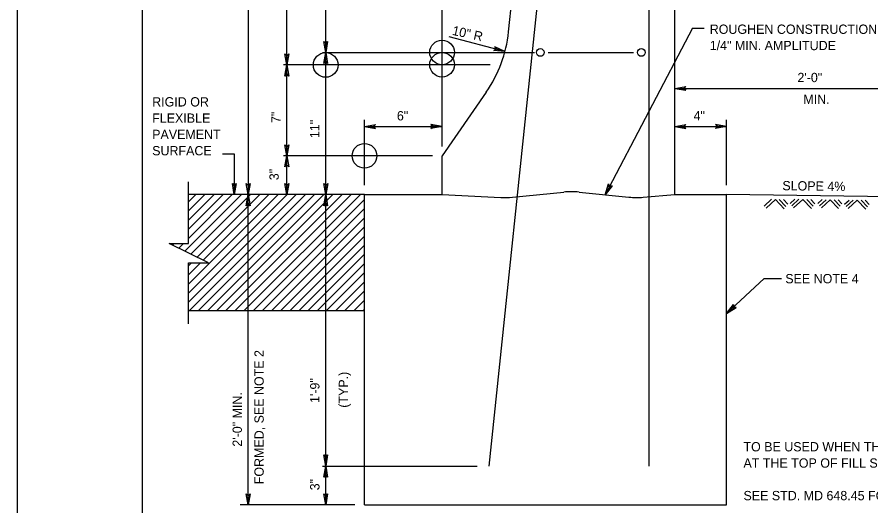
# Model space of a CAD drawing. Extents: x -32.9 to -15.8, y -6.5 to 4.5.
# Drawn here: x -24.32 to -18.82, y -1.37 to 1.78 of the extents above; entities that cross this region are included whole.
import ezdxf

# ---------------------------------------------------------------- set-up
doc = ezdxf.new("R2010")
doc.units = 0
for name, color, linetype in [('ANNO-WOUT', 7, 'Continuous'), ('BORD-LINE', 7, 'Continuous'), ('DETL-DIMS', 7, 'Continuous'), ('Level 1', 7, 'Continuous'), ('Level 10', 7, 'Continuous'), ('Level 12', 7, 'Continuous'), ('Level 6', 7, 'Continuous'), ('SECT-GRND_P', 7, 'Continuous'), ('SUBS-ASLB_P', 7, 'Continuous'), ('SUBS-FOOT_P', 7, 'Continuous'), ('SUPR-PARA_P', 7, 'Continuous'), ('SUPR-RFRC', 7, 'Continuous'), ('USER-CLIP', 7, 'Continuous')]:
    doc.layers.add(name, color=color, linetype=linetype)

msp = doc.modelspace()

# ---------------------------------------------------------------- linework, layer by layer
at = {"layer": 'ANNO-WOUT'}
for centre in [(-21.5854, 1.5558), (-22.3354, 1.4753), (-21.5854, 1.4763), (-22.0854, 0.8891)]:
    msp.add_circle(centre, 0.0795, dxfattribs=at)
at = {"layer": 'BORD-LINE'}
msp.add_lwpolyline([(-23.5151, 4.1733), (-16.1409, 4.1733), (-16.1409, -6.1798), (-23.5151, -6.1798)], close=True, dxfattribs=at)
at = {"layer": 'DETL-DIMS'}
for p, q in [((-22.3354, 1.5558), (-22.3481, 1.6273)), ((-22.3354, 1.6138), (-22.3481, 1.6273)), ((-22.3354, 1.5558), (-22.3229, 1.6273)), ((-22.3229, 1.6273), (-22.3354, 1.6138)), ((-22.5854, 1.4753), (-22.5981, 1.5468)), ((-22.5854, 1.5333), (-22.5981, 1.5468)), ((-22.5854, 1.4753), (-22.5729, 1.5468)), ((-22.5729, 1.5468), (-22.5854, 1.5333)), ((-22.3354, 1.5558), (-22.3479, 1.4843)), ((-22.3354, 1.5558), (-22.3227, 1.4843)), ((-21.2362, 1.5763), (-21.2525, 1.5675)), ((-21.1801, 1.5615), (-21.2525, 1.5675)), ((-21.1801, 1.5615), (-21.246, 1.5918)), ((-21.246, 1.5918), (-21.2362, 1.5763)), ((-22.3479, 1.4843), (-22.3354, 1.4978)), ((-22.3354, 1.4978), (-22.3227, 1.4843)), ((-22.5854, 1.4753), (-22.5979, 1.4038)), ((-22.5854, 1.4753), (-22.5727, 1.4038)), ((-22.5979, 1.4038), (-22.5854, 1.4173)), ((-22.5854, 1.4173), (-22.5727, 1.4038)), ((-20.0854, 1.3241), (-20.0139, 1.3368)), ((-20.0854, 1.3241), (-20.0139, 1.3116)), ((-20.0274, 1.3241), (-20.0139, 1.3368)), ((-20.0139, 1.3116), (-20.0274, 1.3241)), ((-22.0854, 1.0776), (-22.0139, 1.0903)), ((-22.0854, 1.0776), (-22.0139, 1.0651)), ((-22.0274, 1.0776), (-22.0139, 1.0903)), ((-22.0139, 1.0651), (-22.0274, 1.0776)), ((-21.5854, 1.0776), (-21.6569, 1.0901)), ((-21.6569, 1.0901), (-21.6434, 1.0776)), ((-21.5854, 1.0776), (-21.6569, 1.0649)), ((-21.6434, 1.0776), (-21.6569, 1.0649)), ((-20.0854, 1.0776), (-20.0139, 1.0903)), ((-20.0854, 1.0776), (-20.0139, 1.0651)), ((-20.0274, 1.0776), (-20.0139, 1.0903)), ((-20.0139, 1.0651), (-20.0274, 1.0776)), ((-19.752, 1.0776), (-19.8236, 1.0649)), ((-19.81, 1.0776), (-19.8236, 1.0649)), ((-19.752, 1.0776), (-19.8235, 1.0901)), ((-19.8235, 1.0901), (-19.81, 1.0776)), ((-22.5854, 0.8891), (-22.5981, 0.9606)), ((-22.5854, 0.9471), (-22.5981, 0.9606)), ((-22.5854, 0.8891), (-22.5729, 0.9606)), ((-22.5729, 0.9606), (-22.5854, 0.9471)), ((-22.5854, 0.8891), (-22.5979, 0.8176)), ((-22.5854, 0.8891), (-22.5727, 0.8176)), ((-22.5979, 0.8176), (-22.5854, 0.8311)), ((-22.5854, 0.8311), (-22.5727, 0.8176)), ((-22.9241, 0.6391), (-22.9368, 0.7106)), ((-22.9241, 0.6971), (-22.9368, 0.7106)), ((-22.9241, 0.6391), (-22.9116, 0.7106)), ((-22.9116, 0.7106), (-22.9241, 0.6971)), ((-22.8354, 0.6391), (-22.8481, 0.7106)), ((-22.8354, 0.6971), (-22.8481, 0.7106)), ((-22.8354, 0.6391), (-22.8229, 0.7106)), ((-22.8229, 0.7106), (-22.8354, 0.6971)), ((-22.5854, 0.6391), (-22.5981, 0.7106)), ((-22.5854, 0.6971), (-22.5981, 0.7106)), ((-22.5854, 0.6391), (-22.5729, 0.7106)), ((-22.5729, 0.7106), (-22.5854, 0.6971)), ((-22.3348, 0.6391), (-22.3475, 0.7106)), ((-22.3348, 0.6971), (-22.3475, 0.7106)), ((-22.3348, 0.6391), (-22.3223, 0.7106)), ((-22.3223, 0.7106), (-22.3348, 0.6971)), ((-20.5347, 0.6382), (-20.5128, 0.7075)), ((-20.5347, 0.6382), (-20.4905, 0.6958)), ((-20.5078, 0.6896), (-20.5128, 0.7075)), ((-20.4905, 0.6958), (-20.5078, 0.6896)), ((-22.8354, 0.6391), (-22.8479, 0.5676)), ((-22.8354, 0.6391), (-22.8227, 0.5676)), ((-22.3354, 0.6391), (-22.3479, 0.5676)), ((-22.3354, 0.6391), (-22.3227, 0.5676)), ((-22.8479, 0.5676), (-22.8354, 0.5811)), ((-22.8354, 0.5811), (-22.8227, 0.5676)), ((-22.3479, 0.5676), (-22.3354, 0.5811)), ((-22.3354, 0.5811), (-22.3227, 0.5676)), ((-19.752, -0.1283), (-19.7084, -0.0702)), ((-19.752, -0.1283), (-19.6912, -0.0887)), ((-19.7096, -0.0887), (-19.7084, -0.0702)), ((-19.6912, -0.0887), (-19.7096, -0.0887)), ((-22.3354, -1.1109), (-22.3481, -1.0394)), ((-22.3354, -1.0529), (-22.3481, -1.0394)), ((-22.3354, -1.1109), (-22.3229, -1.0394)), ((-22.3229, -1.0394), (-22.3354, -1.0529)), ((-22.3354, -1.1109), (-22.3479, -1.1824)), ((-22.3354, -1.1109), (-22.3227, -1.1824)), ((-22.3479, -1.1824), (-22.3354, -1.1689)), ((-22.3354, -1.1689), (-22.3227, -1.1824)), ((-22.8354, -1.3609), (-22.8481, -1.2894)), ((-22.8354, -1.3029), (-22.8481, -1.2894)), ((-22.8354, -1.3609), (-22.8229, -1.2894)), ((-22.8229, -1.2894), (-22.8354, -1.3029)), ((-22.3354, -1.3609), (-22.3481, -1.2894)), ((-22.3354, -1.3029), (-22.3481, -1.2894)), ((-22.3354, -1.3609), (-22.3229, -1.2894)), ((-22.3229, -1.2894), (-22.3354, -1.3029))]:
    msp.add_line(p, q, dxfattribs=at)
for points in [[(-22.3229, 1.6273), (-22.3354, 1.5558), (-22.3481, 1.6273), (-22.3354, 1.6138)], [(-22.5729, 1.5468), (-22.5854, 1.4753), (-22.5981, 1.5468), (-22.5854, 1.5333)], [(-22.3479, 1.4843), (-22.3354, 1.5558), (-22.3227, 1.4843), (-22.3354, 1.4978)], [(-21.246, 1.5918), (-21.1801, 1.5615), (-21.2525, 1.5675), (-21.2362, 1.5763)], [(-22.5979, 1.4038), (-22.5854, 1.4753), (-22.5727, 1.4038), (-22.5854, 1.4173)], [(-20.0139, 1.3116), (-20.0854, 1.3241), (-20.0139, 1.3368), (-20.0274, 1.3241)], [(-22.0139, 1.0651), (-22.0854, 1.0776), (-22.0139, 1.0903), (-22.0274, 1.0776)], [(-21.6569, 1.0901), (-21.5854, 1.0776), (-21.6569, 1.0649), (-21.6434, 1.0776)], [(-20.0139, 1.0651), (-20.0854, 1.0776), (-20.0139, 1.0903), (-20.0274, 1.0776)], [(-19.8235, 1.0901), (-19.752, 1.0776), (-19.8236, 1.0649), (-19.81, 1.0776)], [(-22.5729, 0.9606), (-22.5854, 0.8891), (-22.5981, 0.9606), (-22.5854, 0.9471)], [(-22.5979, 0.8176), (-22.5854, 0.8891), (-22.5727, 0.8176), (-22.5854, 0.8311)], [(-22.9116, 0.7106), (-22.9241, 0.6391), (-22.9368, 0.7106), (-22.9241, 0.6971)], [(-22.8229, 0.7106), (-22.8354, 0.6391), (-22.8481, 0.7106), (-22.8354, 0.6971)], [(-22.5729, 0.7106), (-22.5854, 0.6391), (-22.5981, 0.7106), (-22.5854, 0.6971)], [(-22.3223, 0.7106), (-22.3348, 0.6391), (-22.3475, 0.7106), (-22.3348, 0.6971)], [(-20.4905, 0.6958), (-20.5347, 0.6382), (-20.5128, 0.7075), (-20.5078, 0.6896)], [(-22.8479, 0.5676), (-22.8354, 0.6391), (-22.8227, 0.5676), (-22.8354, 0.5811)], [(-22.3479, 0.5676), (-22.3354, 0.6391), (-22.3227, 0.5676), (-22.3354, 0.5811)], [(-19.6912, -0.0887), (-19.752, -0.1283), (-19.7084, -0.0702), (-19.7096, -0.0887)], [(-22.3229, -1.0394), (-22.3354, -1.1109), (-22.3481, -1.0394), (-22.3354, -1.0529)], [(-22.3479, -1.1824), (-22.3354, -1.1109), (-22.3227, -1.1824), (-22.3354, -1.1689)], [(-22.8229, -1.2894), (-22.8354, -1.3609), (-22.8481, -1.2894), (-22.8354, -1.3029)], [(-22.3229, -1.2894), (-22.3354, -1.3609), (-22.3481, -1.2894), (-22.3354, -1.3029)]]:
    msp.add_lwpolyline(points, close=True, dxfattribs=at)
at = {"layer": 'Level 1'}
for p, q in [((-23.2193, 0.3243), (-23.2193, 0.7224)), ((-22.0848, -0.1109), (-22.0848, 0.6391)), ((-23.0908, 0.1988), (-23.3446, 0.3243)), ((-23.3446, 0.3243), (-23.2193, 0.3243)), ((-23.2193, -0.1942), (-23.2193, 0.1988)), ((-23.2193, 0.1988), (-23.0908, 0.1988))]:
    msp.add_line(p, q, dxfattribs=at)
at = {"layer": 'Level 10'}
for p, q in [((-21.5854, 0.9491), (-21.5854, 3.9933)), ((-22.8354, 3.4724), (-22.8354, 0.6391)), ((-22.5854, 1.4753), (-22.5854, 3.4724)), ((-22.3354, 1.5558), (-22.3354, 2.4724)), ((-19.9722, 1.7132), (-20.5347, 0.6382)), ((-19.9722, 1.7132), (-19.8969, 1.7132)), ((-21.1801, 1.5615), (-21.5391, 1.6563)), ((-22.3562, 1.5558), (-20.9904, 1.5558)), ((-22.3354, 0.6391), (-22.3354, 1.5558)), ((-20.9029, 1.5558), (-20.352, 1.5558)), ((-21.2753, 1.4753), (-22.6062, 1.4753)), ((-22.5854, 0.8891), (-22.5854, 1.4753)), ((-20.0854, 1.3241), (-18.0854, 1.3241)), ((-22.0848, 0.7004), (-22.0854, 1.1222)), ((-19.752, 0.7003), (-19.752, 1.1222)), ((-22.0854, 1.0776), (-21.5854, 1.0776)), ((-20.0854, 1.0776), (-19.752, 1.0776)), ((-20.0854, 0.6888), (-20.0854, 0.9394)), ((-23, 0.9028), (-22.9241, 0.9028)), ((-22.9241, 0.9028), (-22.9241, 0.6391)), ((-21.6479, 0.8891), (-22.6062, 0.8891)), ((-22.5854, 0.6391), (-22.5854, 0.8891)), ((-22.8354, -1.3609), (-22.8354, 0.6391)), ((-22.3354, -1.1109), (-22.3354, 0.6391)), ((-19.752, -0.1283), (-19.5103, 0.0971)), ((-19.5103, 0.0971), (-19.3976, 0.0971)), ((-22.3562, -1.1109), (-21.36, -1.1109)), ((-22.3354, -1.3609), (-22.3354, -1.1109)), ((-22.1473, -1.3609), (-22.8859, -1.3609))]:
    msp.add_line(p, q, dxfattribs=at)
at = {"layer": 'Level 6'}
for p, q in [((-23.2431, 0.2741), (-22.8782, 0.6391)), ((-23.2193, -0.0555), (-22.5246, 0.6391)), ((-23.2193, 0.4748), (-23.0549, 0.6391)), ((-23.2193, 0.5337), (-23.1139, 0.6391)), ((-23.2193, 0.5926), (-23.1728, 0.6391)), ((-23.2193, 0.0623), (-22.6425, 0.6391)), ((-23.2193, 0.0034), (-22.5835, 0.6391)), ((-23.2193, 0.3569), (-22.9371, 0.6391)), ((-23.2193, 0.4159), (-22.996, 0.6391)), ((-23.2157, -0.1109), (-22.4657, 0.6391)), ((-23.2037, 0.2546), (-22.8192, 0.6391)), ((-23.1643, 0.2352), (-22.7603, 0.6391)), ((-23.1568, -0.1109), (-22.4068, 0.6391)), ((-23.1248, 0.2157), (-22.7014, 0.6391)), ((-23.0978, -0.1109), (-22.3478, 0.6391)), ((-23.0389, -0.1109), (-22.2889, 0.6391)), ((-22.98, -0.1109), (-22.23, 0.6391)), ((-22.921, -0.1109), (-22.171, 0.6391)), ((-22.8621, -0.1109), (-22.1121, 0.6391)), ((-22.8032, -0.1109), (-22.0848, 0.6076)), ((-19.4633, 0.61), (-19.511, 0.5651)), ((-19.4972, 0.5518), (-19.4369, 0.6084)), ((-19.4369, 0.6084), (-19.3802, 0.5479)), ((-19.3705, 0.5625), (-19.4135, 0.6084)), ((-19.3857, 0.6075), (-19.358, 0.578)), ((-19.3427, 0.5819), (-19.3133, 0.6093)), ((-19.2873, 0.609), (-19.3326, 0.5664)), ((-19.32, 0.5536), (-19.2613, 0.6086)), ((-19.2613, 0.6086), (-19.206, 0.5498)), ((-19.1945, 0.5648), (-19.2354, 0.6082)), ((-19.2094, 0.6078), (-19.1837, 0.5806)), ((-19.1637, 0.5815), (-19.1369, 0.6068)), ((-19.1109, 0.6064), (-19.1538, 0.5662)), ((-19.1411, 0.5532), (-19.0849, 0.6061)), ((-19.0849, 0.6061), (-19.0318, 0.5496)), ((-19.0201, 0.5646), (-19.0589, 0.6057)), ((-19.0329, 0.6053), (-19.0094, 0.5805)), ((-18.9924, 0.5769), (-18.963, 0.6043)), ((-18.937, 0.6039), (-18.9825, 0.5614)), ((-18.9698, 0.5486), (-18.9111, 0.6036)), ((-18.9111, 0.6036), (-18.8559, 0.5448)), ((-18.8442, 0.5598), (-18.8851, 0.6032)), ((-18.8591, 0.6028), (-18.8334, 0.5756)), ((-22.7443, -0.1109), (-22.0848, 0.5486)), ((-22.6853, -0.1109), (-22.0848, 0.4897)), ((-22.6264, -0.1109), (-22.0848, 0.4308)), ((-22.5675, -0.1109), (-22.0848, 0.3718)), ((-23.322, 0.3131), (-23.3109, 0.3243)), ((-23.2826, 0.2936), (-23.2519, 0.3243)), ((-22.5086, -0.1109), (-22.0848, 0.3129)), ((-22.4496, -0.1109), (-22.0848, 0.254)), ((-23.2193, 0.1212), (-23.1417, 0.1988)), ((-23.2188, 0.1806), (-23.2006, 0.1988)), ((-22.3907, -0.1109), (-22.0848, 0.1951)), ((-22.3318, -0.1109), (-22.0848, 0.1361)), ((-22.2729, -0.1109), (-22.0848, 0.0772)), ((-22.2139, -0.1109), (-22.0848, 0.0183)), ((-22.155, -0.1109), (-22.0848, -0.0406)), ((-22.0961, -0.1109), (-22.0848, -0.0996))]:
    msp.add_line(p, q, dxfattribs=at)
at = {"layer": 'SECT-GRND_P'}
msp.add_line((-18.0854, 0.6164), (-19.752, 0.6391), dxfattribs=at)
at = {"layer": 'SUBS-ASLB_P'}
for p, q in [((-22.0848, 0.6391), (-23.2193, 0.6391)), ((-22.0848, -0.1109), (-23.2193, -0.1109))]:
    msp.add_line(p, q, dxfattribs=at)
at = {"layer": 'SUBS-FOOT_P'}
for p, q in [((-22.0848, -1.3609), (-22.0848, 0.6391)), ((-22.0848, 0.6391), (-21.5854, 0.6391)), ((-20.0854, 0.6391), (-19.752, 0.6391)), ((-19.752, -1.3609), (-19.752, 0.6391)), ((-22.0848, -1.3609), (-19.752, -1.3609))]:
    msp.add_line(p, q, dxfattribs=at)
for points in [[(-21.5854, 0.6391), (-21.2061, 0.6202)], [(-21.1314, 0.622), (-20.8018, 0.655)], [(-20.7023, 0.655), (-20.381, 0.6228)], [(-20.2897, 0.6221), (-20.0854, 0.6391)]]:
    msp.add_lwpolyline(points, dxfattribs=at)
for centre, start, end in [((-21.1812, 1.1195), 267.1376, 275.7106), ((-20.752, 0.1575), 84.2894, 95.7106), ((-20.3312, 1.1204), 264.2894, 274.7636)]:
    msp.add_arc(centre, 0.5, start, end, dxfattribs=at)
at = {"layer": 'SUPR-PARA_P'}
for p, q in [((-21.157, 1.6879), (-20.9767, 3.4164)), ((-20.0854, 0.6391), (-20.0854, 3.4099)), ((-21.3009, 1.2996), (-21.5854, 0.8891)), ((-21.5854, 0.6391), (-21.5854, 0.8891))]:
    msp.add_line(p, q, dxfattribs=at)
msp.add_arc((-21.9858, 1.7743), 0.8333, 325.2756, 354.0468, dxfattribs=at)
at = {"layer": 'SUPR-RFRC'}
for p, q in [((-21.2812, -1.1109), (-20.846, 3.063)), ((-20.252, -1.1109), (-20.252, 3.0349))]:
    msp.add_line(p, q, dxfattribs=at)
for centre in [(-20.9529, 1.5558), (-20.302, 1.5558)]:
    msp.add_circle(centre, 0.025, dxfattribs=at)
at = {"layer": 'USER-CLIP'}
msp.add_lwpolyline([(-15.824, 4.5033), (-24.324, 4.5033), (-24.324, -6.4967), (-15.824, -6.4967)], close=True, dxfattribs=at)

# ---------------------------------------------------------------- texts
at = {"layer": 'Level 12'}
for s, rotation, p in [('10" R', 347.5221, (-21.5239, 1.67)), ('7"', 90, (-22.6254, 1.1008)), ('11"', 90, (-22.3765, 1.0036)), ('3"', 90, (-22.638, 0.7318)), ('SLOPE 4%', 359.1796, (-19.3931, 0.6673)), ('FORMED, SEE NOTE 2', 90, (-22.7346, -1.2283)), ('1\'-9"', 90, (-22.3755, -0.7045)), ('(TYP.)', 90, (-22.1912, -0.7351)), ('2\'-0" MIN.', 90, (-22.8754, -0.9861)), ('3"', 90, (-22.3755, -1.2676))]:
    msp.add_text(s, height=0.06001, rotation=rotation, dxfattribs=at).set_placement(p)
for s, p in [('ROUGHEN CONSTRUCTION JOINT, ', (-19.8607, 1.6756)), ('1/4" MIN. AMPLITUDE', (-19.8607, 1.5706)), ('2\'-0"', (-19.2957, 1.3642)), ('RIGID OR', (-23.4534, 1.2072)), ('MIN.', (-19.2576, 1.2241)), ('FLEXIBLE', (-23.4534, 1.1022)), ('6"', (-21.8765, 1.1175)), ('4"', (-19.9649, 1.1177)), ('PAVEMENT', (-23.4534, 0.9972)), ('SURFACE', (-23.4534, 0.8922)), ('SEE NOTE 4', (-19.3738, 0.0671)), ('TO BE USED WHEN THE BARRIER IS FREE STANDING (NO BACKING)', (-19.6434, -1.0167)), ('AT THE TOP OF FILL SLOPES.', (-19.6434, -1.1217)), ('SEE STD. MD 648.45 FOR 34 INCH F SHAPE CONCRETE TRAFFIC ', (-19.6434, -1.3317))]:
    msp.add_text(s, height=0.06001, dxfattribs=at).set_placement(p)

doc.saveas('drawing.dxf')
